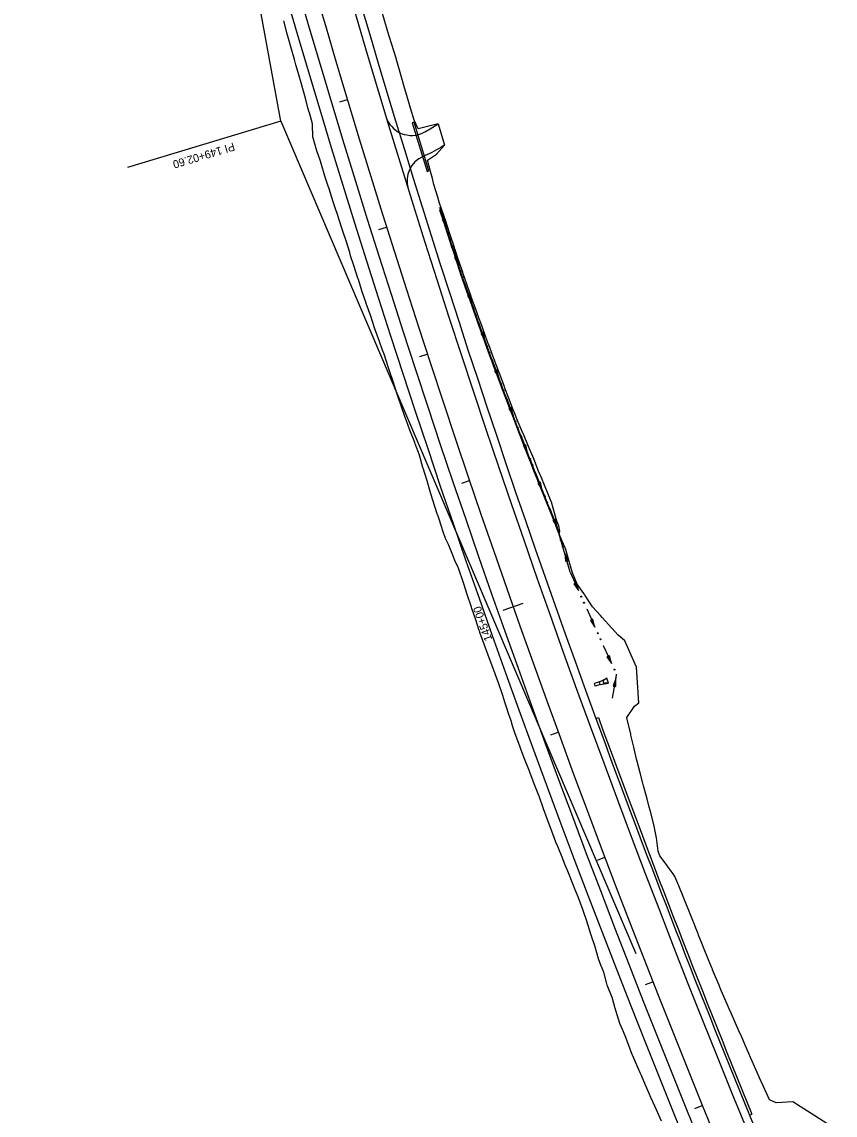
# Model space of a CAD drawing. Extents: x 948761 to 996004, y 1858548 to 1925175.
# Drawn here: x 986412 to 987021, y 1871311 to 1872130 of the extents above; entities that cross this region are included whole.
import ezdxf

# ---------------------------------------------------------------- set-up
doc = ezdxf.new("R2010")
doc.units = 0
for name, color, linetype in [('62', 7, 'Continuous'), ('R_Drainage', 7, 'Continuous'), ('R_Horz Alg', 7, 'Continuous'), ('R_Horz Alg Annot', 7, 'Continuous'), ('R_Proposed Const Limits', 7, 'Continuous'), ('R_Proposed Road', 7, 'Continuous')]:
    doc.layers.add(name, color=color, linetype=linetype)

msp = doc.modelspace()

# ---------------------------------------------------------------- linework, layer by layer
at = {"layer": '62'}
for p, q in [((986728.58, 1871982.74), (986726.57, 1871982.09)), ((986729.43, 1871976.7), (986728.58, 1871982.74)), ((986726.57, 1871982.09), (986729.43, 1871976.7)), ((986737.85, 1871954.18), (986735.84, 1871953.5)), ((986735.84, 1871953.5), (986738.77, 1871948.16)), ((986738.77, 1871948.16), (986737.85, 1871954.18)), ((986747.6, 1871925.78), (986745.6, 1871925.08)), ((986748.58, 1871919.77), (986747.6, 1871925.78)), ((986745.6, 1871925.08), (986748.58, 1871919.77)), ((986757.6, 1871897.47), (986755.61, 1871896.75)), ((986755.61, 1871896.75), (986758.66, 1871891.47)), ((986758.66, 1871891.47), (986757.6, 1871897.47)), ((986767.89, 1871869.26), (986765.91, 1871868.52)), ((986765.91, 1871868.52), (986769.02, 1871863.28)), ((986769.02, 1871863.28), (986767.89, 1871869.26)), ((986778.57, 1871841.19), (986776.59, 1871840.43)), ((986776.59, 1871840.43), (986779.73, 1871835.21)), ((986779.73, 1871835.21), (986778.57, 1871841.19)), ((986789.38, 1871813.18), (986787.41, 1871812.41)), ((986787.41, 1871812.41), (986790.58, 1871807.2)), ((986790.58, 1871807.2), (986789.38, 1871813.18)), ((986800.32, 1871785.21), (986798.35, 1871784.42)), ((986798.35, 1871784.42), (986801.56, 1871779.25)), ((986801.56, 1871779.25), (986800.32, 1871785.21)), ((986811.51, 1871757.34), (986809.55, 1871756.55)), ((986809.55, 1871756.55), (986812.78, 1871751.38)), ((986812.78, 1871751.38), (986811.51, 1871757.34)), ((986822.61, 1871717.54), (986814.31, 1871746.12)), ((986818.43, 1871731.94), (986819.08, 1871725.89)), ((986821.12, 1871726.48), (986818.43, 1871731.94)), ((986819.08, 1871725.89), (986821.12, 1871726.48)), ((986827.25, 1871709.75), (986825.32, 1871708.89)), ((986825.32, 1871708.89), (986828.74, 1871703.85)), ((986828.74, 1871703.85), (986827.25, 1871709.75)), ((986839.53, 1871682.34), (986837.6, 1871681.47)), ((986837.6, 1871681.47), (986841.03, 1871676.44)), ((986841.03, 1871676.44), (986839.53, 1871682.34)), ((986851.97, 1871655.01), (986850.04, 1871654.12)), ((986853.52, 1871649.12), (986851.97, 1871655.01)), ((986850.04, 1871654.12), (986853.52, 1871649.12)), ((986856.69, 1871637.92), (986854.65, 1871632.17)), ((986854.65, 1871632.17), (986856.74, 1871631.82)), ((986856.74, 1871631.82), (986856.69, 1871637.92))]:
    msp.add_line(p, q, dxfattribs=at)
for points in [[(986814.6, 1871746.22), (986814.08, 1871748.15), (986812.53, 1871751.99), (986811.1, 1871755.53), (986807.38, 1871764.76), (986805.63, 1871769.12), (986803.67, 1871774), (986799.96, 1871783.24), (986798.77, 1871786.28), (986798.68, 1871786.5), (986796.33, 1871792.5), (986792.7, 1871801.77), (986792.04, 1871803.48), (986789.08, 1871811.05), (986785.48, 1871820.33), (986785.34, 1871820.69), (986781.89, 1871829.61), (986778.69, 1871837.93), (986778.31, 1871838.9), (986774.75, 1871848.2), (986772.08, 1871855.19), (986771.2, 1871857.5), (986767.68, 1871866.82), (986765.6, 1871872.48), (986764.25, 1871876.16), (986763.6, 1871877.94), (986760.83, 1871885.51), (986759.26, 1871889.83), (986757.42, 1871894.86), (986754.02, 1871904.21), (986752.97, 1871907.2), (986750.73, 1871913.6), (986747.45, 1871923), (986746.88, 1871924.64), (986744.18, 1871932.4), (986740.92, 1871941.8), (986740.82, 1871942.08), (986737.73, 1871951.23), (986734.99, 1871959.61), (986734.64, 1871960.69), (986731.55, 1871970.15), (986729.28, 1871977.17), (986728.48, 1871979.62), (986725.43, 1871989.09), (986724.82, 1871990.98)], [(986724.82, 1871990.98), (986725.43, 1871989.09), (986728.48, 1871979.62), (986729.28, 1871977.17), (986729.43, 1871976.7)], [(986814.13, 1871746.06), (986813.61, 1871747.98), (986812.06, 1871751.82), (986810.63, 1871755.36), (986806.91, 1871764.6), (986805.15, 1871768.96), (986803.2, 1871773.84), (986799.49, 1871783.08), (986798.29, 1871786.11), (986798.2, 1871786.34), (986795.85, 1871792.34), (986792.23, 1871801.61), (986791.56, 1871803.32), (986788.61, 1871810.89), (986785, 1871820.17), (986784.86, 1871820.53), (986781.41, 1871829.45), (986778.21, 1871837.77), (986777.84, 1871838.75), (986774.28, 1871848.04), (986771.61, 1871855.03), (986770.73, 1871857.34), (986767.21, 1871866.66), (986765.13, 1871872.33), (986763.78, 1871876), (986763.12, 1871877.79), (986760.36, 1871885.35), (986758.78, 1871889.68), (986756.95, 1871894.7), (986753.55, 1871904.06), (986752.49, 1871907.05), (986750.25, 1871913.45), (986746.97, 1871922.85), (986746.41, 1871924.48), (986743.7, 1871932.25), (986740.44, 1871941.65), (986740.35, 1871941.93), (986737.25, 1871951.08), (986734.52, 1871959.46), (986734.16, 1871960.54), (986731.07, 1871970), (986728.8, 1871977.02), (986728.01, 1871979.47), (986724.96, 1871988.94)], [(986734.07, 1871962.44), (986734.08, 1871962.41)], [(986734.08, 1871962.41), (986734.64, 1871960.69), (986734.99, 1871959.61), (986737.73, 1871951.23), (986738.77, 1871948.16)], [(986743.64, 1871933.97), (986743.65, 1871933.93)], [(986743.65, 1871933.93), (986744.18, 1871932.4), (986746.88, 1871924.64), (986747.45, 1871923), (986748.58, 1871919.77)], [(986753.53, 1871905.61), (986753.54, 1871905.57)], [(986753.54, 1871905.57), (986754.02, 1871904.21), (986757.42, 1871894.86), (986758.66, 1871891.47)], [(986763.81, 1871877.38), (986763.82, 1871877.35)], [(986763.82, 1871877.35), (986764.25, 1871876.16), (986765.6, 1871872.48), (986767.68, 1871866.82), (986769.02, 1871863.28)], [(986774.35, 1871849.26), (986774.36, 1871849.22)], [(986774.36, 1871849.22), (986774.75, 1871848.2), (986778.31, 1871838.9), (986778.69, 1871837.93), (986779.73, 1871835.21)], [(986785.13, 1871821.22), (986785.15, 1871821.18)], [(986785.15, 1871821.18), (986785.34, 1871820.69), (986785.48, 1871820.33), (986789.08, 1871811.05), (986790.58, 1871807.2)], [(986796.04, 1871793.23), (986796.05, 1871793.2)], [(986796.05, 1871793.2), (986796.33, 1871792.5), (986798.68, 1871786.5), (986798.77, 1871786.28), (986799.96, 1871783.24), (986801.56, 1871779.25)], [(986807.15, 1871765.33), (986807.17, 1871765.29)], [(986807.17, 1871765.29), (986807.38, 1871764.76), (986811.1, 1871755.53), (986812.53, 1871751.99), (986812.78, 1871751.38)], [(986822.61, 1871717.54), (986818.43, 1871731.94)], [(986822.61, 1871717.54), (986828.74, 1871703.85)], [(986834.87, 1871690.16), (986834.88, 1871690.13), (986834.88, 1871690.12)], [(986834.88, 1871690.12), (986838.1, 1871682.95), (986838.17, 1871682.79), (986838.96, 1871681.03), (986841.03, 1871676.44)], [(986847.22, 1871662.78), (986847.24, 1871662.74)], [(986847.24, 1871662.74), (986851.36, 1871653.8), (986853.52, 1871649.12)], [(986854.22, 1871623.12), (986855.39, 1871630.17), (986856.09, 1871634.38), (986857.14, 1871640.66), (986857.22, 1871641.13)], [(986854.22, 1871623.12), (986855.39, 1871630.17), (986856.09, 1871634.38), (986856.69, 1871637.92)]]:
    msp.add_lwpolyline(points, dxfattribs=at)
for centre in [(986731, 1871971.95), (986732.56, 1871967.19), (986740.41, 1871943.43), (986742.04, 1871938.69), (986750.26, 1871915.05), (986751.92, 1871910.32), (986760.41, 1871886.78), (986762.13, 1871882.07), (986770.82, 1871858.61), (986772.61, 1871853.92), (986781.56, 1871830.55), (986783.37, 1871825.88), (986792.44, 1871802.55), (986794.26, 1871797.89), (986803.46, 1871774.61), (986805.33, 1871769.96), (986815.6, 1871741.55), (986817, 1871736.74), (986830.81, 1871699.29), (986832.86, 1871694.72), (986843.12, 1871671.89), (986845.18, 1871667.32), (986855.66, 1871644.6)]:
    msp.add_circle(centre, 0.375, dxfattribs=at)
at = {"layer": 'R_Drainage'}
for p, q in [((986705.53, 1872054.9), (986704.1, 1872054.46)), ((986704.1, 1872054.46), (986715.26, 1872018.14)), ((986716.7, 1872018.58), (986705.53, 1872054.9)), ((986715.26, 1872018.14), (986716.7, 1872018.58)), ((986844.44, 1871635.35), (986840.63, 1871634.14)), ((986841.24, 1871632.23), (986840.63, 1871634.14)), ((986845.05, 1871633.45), (986841.24, 1871632.23)), ((986844.44, 1871635.35), (986849.97, 1871638.17)), ((986845.05, 1871633.45), (986844.44, 1871635.35)), ((986845.05, 1871633.45), (986851.18, 1871634.36)), ((986849.97, 1871638.17), (986847.57, 1871636.47)), ((986851.18, 1871634.36), (986848.25, 1871634.35)), ((986851.18, 1871634.36), (986849.97, 1871638.17))]:
    msp.add_line(p, q, dxfattribs=at)
msp.add_arc((986848.24, 1871635.52), 1.17, 125.23895, 270.1791, dxfattribs=at)
at = {"layer": 'R_Horz Alg'}
msp.add_arc((994885.09, 1874549.52), 8594.37, 190.453455, 203.072581, dxfattribs=at)
at = {"layer": 'R_Horz Alg Annot'}
for q in [(986480.9, 1872732.56), (986871.59, 1871431.67)]:
    msp.add_line((986605.79, 1872055.68), q, dxfattribs=at)
for points in [[(986649.83, 1872070.24), (986655.58, 1872071.97)], [(986605.79, 1872055.68), (986490.89, 1872021.07)], [(986679.24, 1871974.59), (986684.96, 1871976.39)], [(986709.75, 1871879.29), (986715.46, 1871881.15)], [(986741.38, 1871784.35), (986747.06, 1871786.28)], [(986772.21, 1871689.11), (986787.3, 1871694.43)], [(986807.92, 1871595.6), (986813.56, 1871597.66)], [(986842.84, 1871501.82), (986848.45, 1871503.95)], [(986878.84, 1871408.45), (986884.43, 1871410.64)], [(986915.93, 1871315.51), (986921.49, 1871317.77)]]:
    msp.add_lwpolyline(points, dxfattribs=at)
at = {"layer": 'R_Proposed Const Limits'}
for points in [[(986723.64, 1872053.74), (986708.69, 1872050.03), (986705.86, 1872055.94), (986705.64, 1872056.46), (986702.93, 1872065.45), (986702.87, 1872065.64), (986700.14, 1872075), (986697.72, 1872083.37), (986697.38, 1872084.56), (986696.67, 1872087.06), (986694.66, 1872094.13), (986692.57, 1872101.1), (986691.81, 1872103.66), (986688.94, 1872113.19), (986687.22, 1872118.77), (986686.01, 1872122.7), (986683.09, 1872132.21), (986681.81, 1872136.42), (986680.22, 1872141.74), (986677.42, 1872151.28), (986676.59, 1872154.13), (986675.13, 1872159.16)], [(986890.84, 1871306.17), (986887.11, 1871314.65), (986883.29, 1871323.22), (986883.02, 1871323.82), (986881.7, 1871326.77), (986879, 1871333.02), (986875.83, 1871340.3), (986874.98, 1871342.23), (986870.99, 1871351.45), (986868.47, 1871357.42), (986867.18, 1871360.73), (986863.62, 1871370.12), (986861.65, 1871374.76), (986859.74, 1871379.39), (986856.69, 1871388.98), (986856.21, 1871390.69), (986856.05, 1871391.26), (986855.71, 1871392.44), (986853.95, 1871398.69), (986850.28, 1871408.03), (986849.7, 1871410.1), (986847.59, 1871417.75), (986847.26, 1871418.8), (986846.18, 1871421.47), (986846.04, 1871421.83), (986843.92, 1871427.1), (986843.69, 1871427.75), (986841.18, 1871436.8), (986838.15, 1871445.57), (986837.89, 1871446.29), (986834.99, 1871455.92), (986832.52, 1871463.36), (986831.77, 1871465.43), (986828.17, 1871474.8), (986825.75, 1871480.7), (986824.41, 1871484.1), (986820.65, 1871493.41), (986818.75, 1871497.97), (986816.89, 1871502.72), (986813.18, 1871512.04), (986811.86, 1871515.27), (986809.57, 1871521.41), (986806.11, 1871530.83), (986805.36, 1871532.72), (986802.56, 1871540.21), (986799.22, 1871549.68), (986799.01, 1871550.23), (986795.62, 1871559.04), (986792.26, 1871567.59), (986791.95, 1871568.39), (986788.38, 1871577.77), (986785.59, 1871584.98), (986784.76, 1871587.13), (986781.28, 1871596.54), (986779.34, 1871602.52), (986778.19, 1871606.1), (986776.29, 1871611.81), (986774.98, 1871615.61), (986773.48, 1871620.21), (986771.92, 1871625.17), (986768.75, 1871634.69), (986767.58, 1871637.88), (986765.25, 1871644.1), (986761.78, 1871653.52), (986761.08, 1871655.33), (986758.23, 1871662.9), (986754.86, 1871672.36), (986754.71, 1871672.82), (986754.34, 1871673.94), (986751.77, 1871681.91), (986748.85, 1871690.5), (986748.54, 1871691.41), (986745.41, 1871700.94), (986742.98, 1871708.18), (986742.21, 1871710.46), (986739.13, 1871720.01), (986738.22, 1871721.81), (986736.43, 1871725.62), (986735.06, 1871729.22), (986731.22, 1871738.51), (986729.21, 1871742.82), (986727.34, 1871747.79), (986724.28, 1871757.34), (986723.3, 1871760.49), (986723.22, 1871760.72), (986721.12, 1871766.87), (986718.14, 1871776.46), (986717.63, 1871778.23), (986715.35, 1871786.11), (986712.28, 1871795.66), (986712.16, 1871796.04), (986709.5, 1871805.31), (986706.44, 1871813.76), (986706.07, 1871814.75), (986702.42, 1871824.11), (986699.86, 1871831.2), (986698.98, 1871833.54), (986695.67, 1871843.02), (986693.68, 1871848.77), (986692.5, 1871852.54), (986691.93, 1871854.37), (986689.33, 1871862.06), (986687.8, 1871866.44), (986686.17, 1871871.58), (986683.12, 1871881.15), (986682.01, 1871884.14), (986679.62, 1871890.56), (986676.25, 1871900.02), (986675.7, 1871901.68), (986673.1, 1871909.55), (986669.76, 1871919.02), (986669.66, 1871919.3), (986666.47, 1871928.51), (986663.83, 1871936.99), (986663.51, 1871938.1), (986660.33, 1871947.62), (986658, 1871954.69), (986657.32, 1871957.19), (986654.36, 1871966.78), (986652.38, 1871972.44), (986651.15, 1871976.3), (986648.06, 1871985.85), (986646.63, 1871990.16), (986644.97, 1871995.4), (986641.99, 1872004.98), (986640.94, 1872007.9), (986638.74, 1872014.49), (986635.88, 1872024.11), (986635.33, 1872025.67), (986632.64, 1872033.61), (986632.48, 1872034.16), (986629.86, 1872043.26), (986629.81, 1872043.46), (986629.56, 1872053.66), (986627.15, 1872062.11), (986626.8, 1872063.31), (986626.08, 1872065.83), (986624.14, 1872072.99), (986622.15, 1872080.05), (986621.41, 1872082.65), (986618.69, 1872092.3), (986617.04, 1872097.96), (986615.96, 1872101.96), (986613.24, 1872111.62), (986611.98, 1872115.88), (986610.53, 1872121.28), (986607.94, 1872130.98)], [(986726.36, 1871989.38), (986724.47, 1871995.01), (986723.29, 1871998.84), (986720.38, 1872008.36), (986719.27, 1872012.73), (986717.8, 1872017.97), (986715.51, 1872026.52), (986722.44, 1872031.04), (986728.29, 1872037.84)], [(986814.31, 1871746.12), (986814.74, 1871748.38), (986813.94, 1871752.48), (986812.42, 1871755.99), (986809.77, 1871765.58), (986808.6, 1871770.15), (986806.51, 1871774.97), (986802.75, 1871784.19), (986801.53, 1871787.22), (986801.44, 1871787.44), (986798.87, 1871793.37), (986795.17, 1871802.61), (986794.48, 1871804.3), (986791.22, 1871811.77), (986787.52, 1871821.02), (986787.36, 1871821.38), (986783.54, 1871830.17), (986780.26, 1871838.45), (986779.87, 1871839.43), (986776.25, 1871848.7), (986773.66, 1871855.71), (986772.79, 1871858.03), (986769.19, 1871867.31), (986767.08, 1871872.97), (986765.78, 1871876.66), (986765.13, 1871878.45), (986762.27, 1871885.98), (986760.65, 1871890.29), (986758.81, 1871895.31), (986755.45, 1871904.68), (986754.36, 1871907.65), (986752.02, 1871914.02), (986748.66, 1871923.39), (986748.08, 1871925.02), (986745.36, 1871932.78), (986742.08, 1871942.18), (986741.99, 1871942.46), (986738.85, 1871951.59), (986736.08, 1871959.95), (986735.73, 1871961.04), (986732.58, 1871970.48), (986730.28, 1871977.48), (986729.47, 1871979.93), (986726.36, 1871989.38)], [(986827.68, 1871708.67), (986824.34, 1871717.03), (986824.07, 1871717.94), (986821.26, 1871727.49), (986819.12, 1871734.75), (986814.31, 1871746.12)], [(986872.17, 1871646.55), (986863.42, 1871666.23), (986861.38, 1871667.96), (986858.57, 1871670.51), (986853.78, 1871675.78), (986846.55, 1871683.74), (986845.15, 1871685.28), (986839.31, 1871691.7), (986833.68, 1871700.25), (986833.39, 1871700.66), (986832.68, 1871701.65), (986827.68, 1871708.67)], [(987020.98, 1871300.44), (987002.92, 1871311.69), (986989.26, 1871320.68), (986976.73, 1871319.71), (986971.94, 1871322.05), (986969.71, 1871326.6), (986965.63, 1871335.68), (986965.3, 1871336.38), (986961.58, 1871344.77), (986957.87, 1871353.29), (986957.6, 1871353.89), (986956.33, 1871356.82), (986953.63, 1871363.01), (986950.49, 1871370.21), (986949.62, 1871372.12), (986945.64, 1871381.23), (986943.08, 1871387.13), (986941.67, 1871390.36), (986937.69, 1871399.48), (986935.71, 1871404.06), (986933.74, 1871408.62), (986929.9, 1871417.8), (986929.24, 1871419.43), (986929.02, 1871419.96), (986928.57, 1871421.09), (986926.17, 1871427.02), (986922.47, 1871436.25), (986921.68, 1871438.22), (986918.74, 1871445.48), (986918.33, 1871446.49), (986917.27, 1871449.13), (986917.12, 1871449.48), (986915.04, 1871454.71), (986914.79, 1871455.35), (986911.32, 1871463.94), (986907.92, 1871472.48), (986907.64, 1871473.18), (986903.93, 1871482.41), (986900.82, 1871489.54), (986899.57, 1871491.4), (986896.62, 1871495.6), (986893.67, 1871499.8), (986889.66, 1871505.04), (986888.43, 1871508.45), (986887.1, 1871518.59), (986886.27, 1871523.51), (986885.19, 1871528.51), (986882.65, 1871538.18), (986881.75, 1871541.54), (986880.05, 1871547.84), (986877.4, 1871557.46), (986876.88, 1871559.42), (986874.81, 1871567.11), (986872.42, 1871576.83), (986872.28, 1871577.41), (986870.11, 1871586.58), (986868.02, 1871595.5), (986867.83, 1871596.34), (986865.55, 1871606.09), (986864.92, 1871608.73), (986870.75, 1871617.22), (986873.96, 1871619.75), (986872.17, 1871646.55)]]:
    msp.add_lwpolyline(points, dxfattribs=at)
at = {"layer": 'R_Proposed Road'}
for p, q in [((986717.49, 1872050), (986723.64, 1872053.74)), ((986723.64, 1872053.74), (986728.29, 1872037.84)), ((986728.29, 1872037.84), (986725.8, 1872036.33)), ((986841.73, 1871607.96), (986843.61, 1871608.65)), ((986956.81, 1871310.59), (986958.66, 1871311.34))]:
    msp.add_line(p, q, dxfattribs=at)
for centre, radius, start, end in [((994885.09, 1874549.52), 8570.37, 190.453455, 203.072581), ((994885.09, 1874549.52), 8564.37, 190.453455, 200.088068), ((994885.09, 1874549.52), 8616.37, 190.453455, 203.072581), ((994885.09, 1874549.52), 8606.37, 190.453455, 203.072581), ((986703.62, 1872065.11), 20, 196.89157, 298.0901), ((986669.72, 1872128.63), 92, 298.0901, 301.28209), ((986669.72, 1872128.63), 108, 293.24755, 301.28209), ((986720.24, 1872011.02), 20, 113.24755, 197.27074), ((994885.09, 1874549.52), 8564.37, 200.088068, 202.221401), ((994885.09, 1874549.52), 8562.37, 200.088068, 202.221401), ((994885.09, 1874549.52), 8564.37, 202.221401, 203.072581)]:
    msp.add_arc(centre, radius, start, end, dxfattribs=at)

# ---------------------------------------------------------------- texts
at = {"layer": 'R_Horz Alg Annot'}
for s, rotation, p in [('PI 149+02.60', 196.76302, (986570.16, 1872039.72)), ('145+00', 109.4214, (986764.23, 1871667.25))]:
    msp.add_text(s, height=6, rotation=rotation, dxfattribs=at).set_placement(p)

doc.saveas('drawing.dxf')
